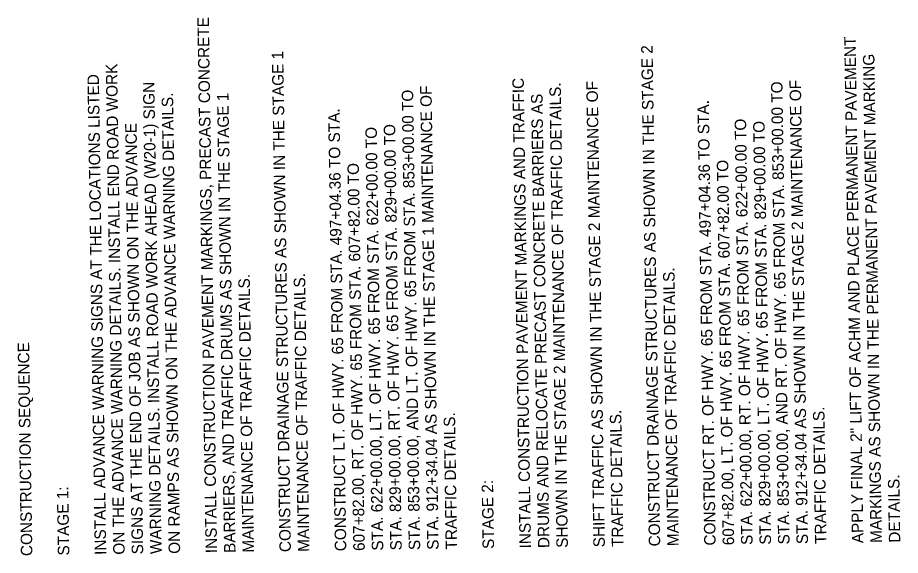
# Model space of a CAD drawing. Extents: x 1770018 to 1773492, y 718230 to 729141.
# Drawn here: x 1770139 to 1770754, y 722949 to 723323 of the extents above; entities that cross this region are included whole.
import ezdxf

# ---------------------------------------------------------------- set-up
doc = ezdxf.new("R2010")
doc.units = 0
doc.layers.add('R_Border Notes', color=7, linetype='Continuous')

msp = doc.modelspace()

# ---------------------------------------------------------------- texts
at = {"layer": 'R_Border Notes'}
for s, p in [('INSTALL CONSTRUCTION PAVEMENT MARKINGS, PRECAST CONCRETE ', (1770277.64, 722950.11)), ('APPLY FINAL 2" LIFT OF ACHM AND PLACE PERMANENT PAVEMENT', (1770728.27, 722957.05)), ('CONSTRUCT DRAINAGE STRUCTURES AS SHOWN IN THE STAGE 1', (1770329.14, 722950.9)), ('CONSTRUCT DRAINAGE STRUCTURES AS SHOWN IN THE STAGE 2', (1770586.65, 722954.87)), ('MARKINGS AS SHOWN IN THE PERMANENT PAVEMENT MARKING ', (1770741.15, 722957.25)), ('ON THE ADVANCE WARNING DETAILS. INSTALL END ROAD WORK ', (1770213.26, 722949.11)), ('INSTALL ADVANCE WARNING SIGNS AT THE LOCATIONS LISTED ', (1770200.39, 722948.92)), ('INSTALL CONSTRUCTION PAVEMENT MARKINGS AND TRAFFIC ', (1770496.52, 722953.48)), ('WARNING DETAILS. INSTALL ROAD WORK AHEAD (W20-1) SIGN ', (1770239.01, 722949.51)), ('STA. 912+34.04 AS SHOWN IN THE STAGE 1 MAINTENANCE OF ', (1770432.14, 722952.49)), ('SHOWN IN THE STAGE 2 MAINTENANCE OF TRAFFIC DETAILS.', (1770522.27, 722953.88)), ('SHIFT TRAFFIC AS SHOWN IN THE STAGE 2 MAINTENANCE OF ', (1770548.02, 722954.27)), ('STA. 853+00.00, AND RT. OF HWY. 65 FROM STA. 853+00.00 TO', (1770676.77, 722956.26)), ('STA. 912+34.04 AS SHOWN IN THE STAGE 2 MAINTENANCE OF ', (1770689.65, 722956.45)), ('ON RAMPS AS SHOWN ON THE ADVANCE WARNING DETAILS. ', (1770251.89, 722949.71)), ('BARRIERS, AND TRAFFIC DRUMS AS SHOWN IN THE STAGE 1 ', (1770290.51, 722950.3)), ('STA. 853+00.00, AND LT. OF HWY. 65 FROM STA. 853+00.00 TO', (1770419.27, 722952.29)), ('DRUMS AND RELOCATE PRECAST CONCRETE BARRIERS AS ', (1770509.39, 722953.68)), ('CONSTRUCT RT. OF HWY. 65 FROM STA. 497+04.36 TO STA. ', (1770625.27, 722955.46)), ('CONSTRUCT LT. OF HWY. 65 FROM STA. 497+04.36 TO STA. ', (1770367.77, 722951.49)), ('STA. 622+00.00, RT. OF HWY. 65 FROM STA. 622+00.00 TO ', (1770651.02, 722955.86)), ('STA. 829+00.00, LT. OF HWY. 65 FROM STA. 829+00.00 TO', (1770663.9, 722956.06)), ('SIGNS AT THE END OF JOB AS SHOWN ON THE ADVANCE ', (1770226.14, 722949.31)), ('STA. 622+00.00, LT. OF HWY. 65 FROM STA. 622+00.00 TO ', (1770393.52, 722951.89)), ('STA. 829+00.00, RT. OF HWY. 65 FROM STA. 829+00.00 TO', (1770406.39, 722952.09)), ('607+82.00, RT. OF HWY. 65 FROM STA. 607+82.00 TO ', (1770380.64, 722951.69)), ('607+82.00, LT. OF HWY. 65 FROM STA. 607+82.00 TO ', (1770638.15, 722955.66)), ('MAINTENANCE OF TRAFFIC DETAILS.', (1770599.52, 722955.07)), ('MAINTENANCE OF TRAFFIC DETAILS.', (1770303.39, 722950.5)), ('MAINTENANCE OF TRAFFIC DETAILS.', (1770342.01, 722951.1)), ('CONSTRUCTION SEQUENCE', (1770148.89, 722948.12)), ('TRAFFIC DETAILS.', (1770445.02, 722952.69)), ('TRAFFIC DETAILS.', (1770560.89, 722954.47)), ('TRAFFIC DETAILS.', (1770702.52, 722956.65)), ('STAGE 2:', (1770470.77, 722953.08)), ('DETAILS.', (1770754.02, 722957.45)), ('STAGE 1:', (1770174.64, 722948.52))]:
    msp.add_text(s, height=8, rotation=90.88269, dxfattribs=at).set_placement(p)

doc.saveas('drawing.dxf')
